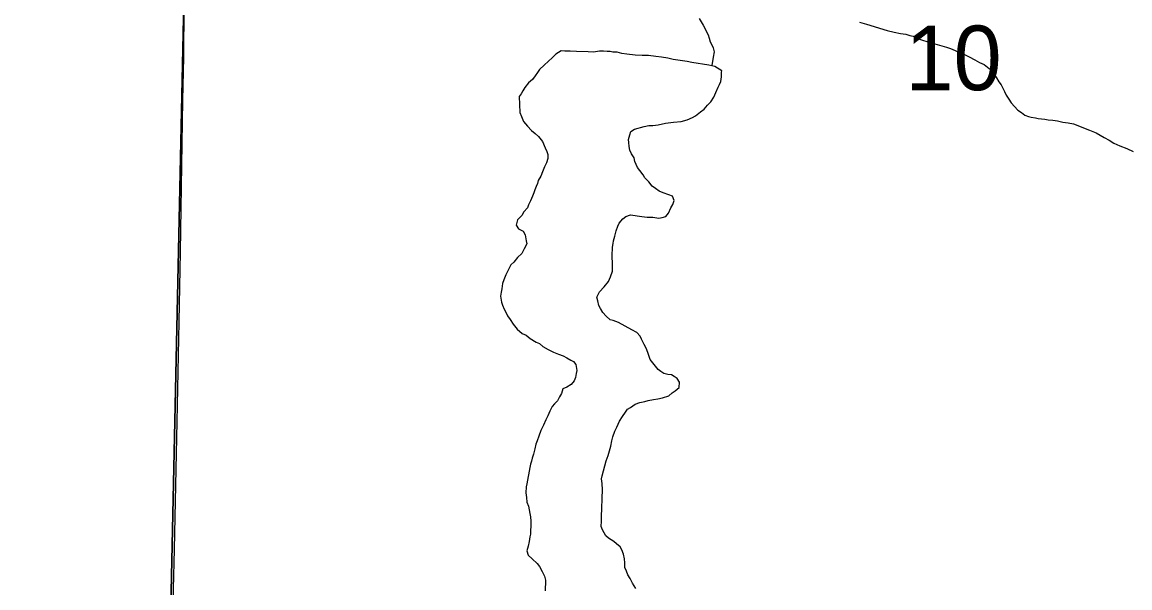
# Model space of a CAD drawing. Extents: x 2.4 to 73.1, y 4.5 to 25.6.
# Drawn here: x 34.9553 to 35.314, y 20.625 to 20.8082 of the extents above; entities that cross this region are included whole.
import ezdxf

# ---------------------------------------------------------------- set-up
doc = ezdxf.new("R2010")
doc.units = 0
for name, color, linetype in [('GM_X_County_Road', 7, 'Continuous'), ('GM_X_Minor_Lake', 7, 'Continuous'), ('GM_X_Minor_River', 7, 'Continuous'), ('GM_X_Section', 7, 'Continuous'), ('GM_X_Section_Text', 7, 'Continuous')]:
    doc.layers.add(name, color=color, linetype=linetype)

msp = doc.modelspace()

# ---------------------------------------------------------------- linework, layer by layer
at = {"layer": 'GM_X_County_Road'}
msp.add_lwpolyline([(35.00289, 20.55796), (35.00312, 20.57408), (35.00389, 20.61013), (35.00423, 20.62473), (35.00454, 20.63747), (35.00505, 20.65829), (35.00549, 20.6788), (35.00608, 20.71112), (35.00648, 20.73381), (35.00729, 20.78291), (35.0076, 20.79689), (35.00777, 20.81337), (35.00799, 20.82704), (35.00828, 20.84818), (35.00866, 20.87273), (35.00899, 20.89821), (35.00925, 20.9125), (35.00984, 20.94327), (35.0103, 20.96409), (35.01067, 20.98398), (35.01061, 20.98712), (35.01051, 20.99209)], dxfattribs=at)
at = {"layer": 'GM_X_Minor_Lake'}
for points in [[(35.18179, 20.79245), (35.17955, 20.7938), (35.17766, 20.79424), (35.17216, 20.79518), (35.17065, 20.79542), (35.16913, 20.79566), (35.16762, 20.7959), (35.1661, 20.79614), (35.1644, 20.79658), (35.16232, 20.79684), (35.16042, 20.79709), (35.15814, 20.79736), (35.15605, 20.79743), (35.15377, 20.7975), (35.15111, 20.79778), (35.1494, 20.79803), (35.14789, 20.79846), (35.14656, 20.7985), (35.14562, 20.79872), (35.14467, 20.79875), (35.14353, 20.79879), (35.14219, 20.79884), (35.14028, 20.79852), (35.13857, 20.79858), (35.13476, 20.7987), (35.13267, 20.79877), (35.13096, 20.79883), (35.12982, 20.79887), (35.12807, 20.79778), (35.12689, 20.79668), (35.12571, 20.79558), (35.12434, 20.79429), (35.12277, 20.79282), (35.12217, 20.79189), (35.12137, 20.79077), (35.12057, 20.78966), (35.11921, 20.78856), (35.11802, 20.78708), (35.11741, 20.78596), (35.11681, 20.78503), (35.11621, 20.7841), (35.11642, 20.77895), (35.11695, 20.7776), (35.11766, 20.77606), (35.11895, 20.77449), (35.12024, 20.77312), (35.12135, 20.77213), (35.12246, 20.77114), (35.12374, 20.76958), (35.12462, 20.76746), (35.12516, 20.7663), (35.12551, 20.76534), (35.12547, 20.76401), (35.12504, 20.76269), (35.12443, 20.76138), (35.12381, 20.75969), (35.12319, 20.75837), (35.12238, 20.75688), (35.12216, 20.75594), (35.12175, 20.755), (35.12133, 20.75387), (35.12092, 20.75293), (35.12051, 20.75181), (35.11989, 20.7503), (35.11928, 20.74899), (35.11886, 20.74806), (35.11768, 20.74676), (35.11707, 20.74564), (35.11569, 20.74416), (35.11526, 20.74247), (35.11598, 20.7413), (35.11748, 20.74049), (35.1182, 20.73932), (35.11852, 20.73741), (35.11868, 20.73646), (35.11787, 20.73477), (35.11706, 20.73328), (35.11569, 20.73199), (35.1145, 20.73051), (35.11351, 20.72959), (35.1127, 20.72809), (35.11189, 20.72641), (35.11126, 20.72472), (35.11085, 20.72359), (35.1106, 20.72188), (35.11037, 20.72075), (35.11014, 20.71943), (35.11046, 20.71751), (35.11081, 20.71655), (35.11134, 20.7152), (35.11188, 20.71423), (35.11242, 20.71307), (35.11333, 20.7119), (35.11423, 20.71035), (35.11551, 20.70879), (35.11718, 20.7074), (35.1185, 20.70679), (35.1198, 20.70579), (35.12167, 20.70459), (35.12279, 20.70417), (35.12391, 20.70318)], [(35.18179, 20.79245), (35.17955, 20.7938), (35.17766, 20.79424), (35.17216, 20.79518), (35.17065, 20.79542), (35.16913, 20.79566), (35.16762, 20.7959), (35.1661, 20.79614), (35.1644, 20.79658), (35.16232, 20.79684), (35.16042, 20.79709), (35.15814, 20.79736), (35.15605, 20.79743), (35.15377, 20.7975), (35.15111, 20.79778), (35.1494, 20.79803), (35.14789, 20.79846), (35.14656, 20.7985), (35.14562, 20.79872), (35.14467, 20.79875), (35.14353, 20.79879), (35.14219, 20.79884), (35.14028, 20.79852), (35.13857, 20.79858), (35.13476, 20.7987), (35.13267, 20.79877), (35.13096, 20.79883), (35.12982, 20.79887), (35.12807, 20.79778), (35.12689, 20.79668), (35.12571, 20.79558), (35.12434, 20.79429), (35.12277, 20.79282), (35.12217, 20.79189), (35.12137, 20.79077), (35.12057, 20.78966), (35.11921, 20.78856), (35.11802, 20.78708), (35.11741, 20.78596), (35.11681, 20.78503), (35.11621, 20.7841), (35.11642, 20.77895), (35.11695, 20.7776), (35.11766, 20.77606), (35.11895, 20.77449), (35.12024, 20.77312), (35.12135, 20.77213), (35.12246, 20.77114), (35.12374, 20.76958), (35.12462, 20.76746), (35.12516, 20.7663), (35.12551, 20.76534), (35.12547, 20.76401), (35.12504, 20.76269), (35.12443, 20.76138), (35.12381, 20.75969), (35.12319, 20.75837), (35.12238, 20.75688), (35.12216, 20.75594), (35.12175, 20.755), (35.12133, 20.75387), (35.12092, 20.75293), (35.12051, 20.75181), (35.11989, 20.7503), (35.11928, 20.74899), (35.11886, 20.74806), (35.11768, 20.74676), (35.11707, 20.74564), (35.11569, 20.74416), (35.11526, 20.74247), (35.11598, 20.7413), (35.11748, 20.74049), (35.1182, 20.73932), (35.11852, 20.73741), (35.11868, 20.73646), (35.11787, 20.73477), (35.11706, 20.73328), (35.11569, 20.73199), (35.1145, 20.73051), (35.11351, 20.72959), (35.1127, 20.72809), (35.11189, 20.72641), (35.11126, 20.72472), (35.11085, 20.72359), (35.1106, 20.72188), (35.11037, 20.72075), (35.11014, 20.71943), (35.11046, 20.71751), (35.11081, 20.71655), (35.11134, 20.7152), (35.11188, 20.71423), (35.11242, 20.71307), (35.11333, 20.7119), (35.11423, 20.71035), (35.11551, 20.70879), (35.11718, 20.7074), (35.1185, 20.70679), (35.1198, 20.70579), (35.12167, 20.70459), (35.12279, 20.70417), (35.12391, 20.70318)], [(35.15156, 20.77018), (35.15199, 20.77169), (35.15241, 20.77282), (35.15357, 20.77354), (35.15665, 20.77439), (35.15818, 20.77472), (35.15951, 20.77468), (35.16124, 20.775), (35.16354, 20.77549), (35.16621, 20.77579), (35.1687, 20.77608), (35.17062, 20.77659), (35.17235, 20.7773), (35.17332, 20.77783), (35.17489, 20.77911), (35.17606, 20.78003), (35.17724, 20.78132), (35.17823, 20.78243), (35.17923, 20.78392), (35.17985, 20.78542), (35.18067, 20.7871), (35.18108, 20.78804), (35.18149, 20.78898), (35.18173, 20.79049), (35.18177, 20.79201), (35.18179, 20.79245)], [(35.15156, 20.77018), (35.15199, 20.77169), (35.15241, 20.77282), (35.15357, 20.77354), (35.15665, 20.77439), (35.15818, 20.77472), (35.15951, 20.77468), (35.16124, 20.775), (35.16354, 20.77549), (35.16621, 20.77579), (35.1687, 20.77608), (35.17062, 20.77659), (35.17235, 20.7773), (35.17332, 20.77783), (35.17489, 20.77911), (35.17606, 20.78003), (35.17724, 20.78132), (35.17823, 20.78243), (35.17923, 20.78392), (35.17985, 20.78542), (35.18067, 20.7871), (35.18108, 20.78804), (35.18149, 20.78898), (35.18173, 20.79049), (35.18177, 20.79201), (35.18179, 20.79245)], [(35.14298, 20.65062), (35.14309, 20.65404), (35.14318, 20.6567), (35.14305, 20.6588), (35.14291, 20.66032), (35.14313, 20.66127), (35.14443, 20.66617), (35.14506, 20.66786), (35.14549, 20.66937), (35.14591, 20.67088), (35.14616, 20.67258), (35.14658, 20.6739), (35.14721, 20.67578), (35.14783, 20.67709), (35.14865, 20.67897), (35.14965, 20.68046), (35.15065, 20.68195), (35.15125, 20.68288), (35.15222, 20.68341), (35.15378, 20.6845), (35.15532, 20.68503), (35.15685, 20.68535), (35.158, 20.6857), (35.15973, 20.68602), (35.16107, 20.68617), (35.1626, 20.6865), (35.16472, 20.68719), (35.1657, 20.68811), (35.16667, 20.68883), (35.16804, 20.68993), (35.1681, 20.69164), (35.16737, 20.69281), (35.16644, 20.69341), (35.16551, 20.69401), (35.16436, 20.69405), (35.16304, 20.69447), (35.16211, 20.69507), (35.16118, 20.69567), (35.15862, 20.69899), (35.1581, 20.70053), (35.1574, 20.70246), (35.15668, 20.70381), (35.15578, 20.70556), (35.15543, 20.70652), (35.15433, 20.7077), (35.15264, 20.70851), (35.15058, 20.70972), (35.14834, 20.71094), (35.14664, 20.71156), (35.1457, 20.71179), (35.1444, 20.71297), (35.1433, 20.71415), (35.14258, 20.7155), (35.14204, 20.71647), (35.14171, 20.718), (35.14136, 20.71916), (35.14218, 20.72084), (35.14376, 20.7225), (35.14514, 20.72417), (35.14576, 20.72567), (35.14639, 20.72755), (35.14646, 20.72983), (35.14636, 20.7325), (35.14645, 20.73535), (35.14668, 20.73648), (35.14671, 20.73743), (35.14714, 20.73894), (35.14757, 20.74064), (35.14819, 20.74214), (35.1486, 20.74308), (35.14979, 20.74456), (35.15077, 20.74529), (35.15231, 20.74581), (35.15591, 20.74531), (35.15761, 20.74506), (35.15952, 20.745), (35.16141, 20.74475), (35.16256, 20.7449), (35.16371, 20.74524), (35.16451, 20.74636), (35.16533, 20.74804), (35.16593, 20.74916), (35.16636, 20.75048), (35.16583, 20.75183), (35.1647, 20.75225), (35.16282, 20.75288), (35.1615, 20.75349), (35.16039, 20.75429), (35.15927, 20.75509), (35.15817, 20.75646), (35.15688, 20.75783), (35.15634, 20.7588), (35.15524, 20.76017), (35.15451, 20.76114), (35.15362, 20.76308), (35.15347, 20.76422), (35.15256, 20.76558), (35.15202, 20.76674), (35.15187, 20.76789), (35.15172, 20.76923), (35.15156, 20.77018)], [(35.14298, 20.65062), (35.14309, 20.65404), (35.14318, 20.6567), (35.14305, 20.6588), (35.14291, 20.66032), (35.14313, 20.66127), (35.14443, 20.66617), (35.14506, 20.66786), (35.14549, 20.66937), (35.14591, 20.67088), (35.14616, 20.67258), (35.14658, 20.6739), (35.14721, 20.67578), (35.14783, 20.67709), (35.14865, 20.67897), (35.14965, 20.68046), (35.15065, 20.68195), (35.15125, 20.68288), (35.15222, 20.68341), (35.15378, 20.6845), (35.15532, 20.68503), (35.15685, 20.68535), (35.158, 20.6857), (35.15973, 20.68602), (35.16107, 20.68617), (35.1626, 20.6865), (35.16472, 20.68719), (35.1657, 20.68811), (35.16667, 20.68883), (35.16804, 20.68993), (35.1681, 20.69164), (35.16737, 20.69281), (35.16644, 20.69341), (35.16551, 20.69401), (35.16436, 20.69405), (35.16304, 20.69447), (35.16211, 20.69507), (35.16118, 20.69567), (35.15862, 20.69899), (35.1581, 20.70053), (35.1574, 20.70246), (35.15668, 20.70381), (35.15578, 20.70556), (35.15543, 20.70652), (35.15433, 20.7077), (35.15264, 20.70851), (35.15058, 20.70972), (35.14834, 20.71094), (35.14664, 20.71156), (35.1457, 20.71179), (35.1444, 20.71297), (35.1433, 20.71415), (35.14258, 20.7155), (35.14204, 20.71647), (35.14171, 20.718), (35.14136, 20.71916), (35.14218, 20.72084), (35.14376, 20.7225), (35.14514, 20.72417), (35.14576, 20.72567), (35.14639, 20.72755), (35.14646, 20.72983), (35.14636, 20.7325), (35.14645, 20.73535), (35.14668, 20.73648), (35.14671, 20.73743), (35.14714, 20.73894), (35.14757, 20.74064), (35.14819, 20.74214), (35.1486, 20.74308), (35.14979, 20.74456), (35.15077, 20.74529), (35.15231, 20.74581), (35.15591, 20.74531), (35.15761, 20.74506), (35.15952, 20.745), (35.16141, 20.74475), (35.16256, 20.7449), (35.16371, 20.74524), (35.16451, 20.74636), (35.16533, 20.74804), (35.16593, 20.74916), (35.16636, 20.75048), (35.16583, 20.75183), (35.1647, 20.75225), (35.16282, 20.75288), (35.1615, 20.75349), (35.16039, 20.75429), (35.15927, 20.75509), (35.15817, 20.75646), (35.15688, 20.75783), (35.15634, 20.7588), (35.15524, 20.76017), (35.15451, 20.76114), (35.15362, 20.76308), (35.15347, 20.76422), (35.15256, 20.76558), (35.15202, 20.76674), (35.15187, 20.76789), (35.15172, 20.76923), (35.15156, 20.77018)], [(35.12391, 20.70318), (35.12559, 20.70218), (35.12728, 20.70136), (35.12897, 20.70073), (35.13047, 20.70011), (35.1316, 20.6995), (35.1329, 20.6987), (35.13384, 20.69829), (35.13457, 20.69731), (35.13489, 20.6954), (35.13467, 20.69446), (35.13444, 20.69313), (35.13402, 20.69201), (35.13303, 20.6909), (35.13167, 20.68999), (35.13032, 20.68947), (35.12989, 20.68796), (35.12929, 20.68684), (35.12867, 20.68552), (35.12769, 20.68461), (35.1269, 20.68368), (35.12609, 20.68219), (35.12547, 20.68068), (35.12486, 20.67937), (35.12404, 20.67769), (35.12323, 20.676), (35.1226, 20.67412), (35.12198, 20.67262), (35.12156, 20.67149), (35.12132, 20.66998), (35.12089, 20.66828), (35.12046, 20.66696), (35.12024, 20.66602), (35.11983, 20.66508), (35.11961, 20.66395), (35.11867, 20.65865), (35.11845, 20.65771), (35.11839, 20.65581), (35.11853, 20.65428), (35.11868, 20.65275), (35.11921, 20.65141), (35.1197, 20.64911), (35.11986, 20.64796), (35.12, 20.64662), (35.11997, 20.64567), (35.11994, 20.64472), (35.11991, 20.64377), (35.11987, 20.64244), (35.11965, 20.6415), (35.11941, 20.63998), (35.11917, 20.63847), (35.11874, 20.63696), (35.11908, 20.63562), (35.12038, 20.63444), (35.12204, 20.63286), (35.12277, 20.63188), (35.12367, 20.63033), (35.12439, 20.62879), (35.12472, 20.62744), (35.12469, 20.6263), (35.12465, 20.62516), (35.12461, 20.62402)], [(35.12391, 20.70318), (35.12559, 20.70218), (35.12728, 20.70136), (35.12897, 20.70073), (35.13047, 20.70011), (35.1316, 20.6995), (35.1329, 20.6987), (35.13384, 20.69829), (35.13457, 20.69731), (35.13489, 20.6954), (35.13467, 20.69446), (35.13444, 20.69313), (35.13402, 20.69201), (35.13303, 20.6909), (35.13167, 20.68999), (35.13032, 20.68947), (35.12989, 20.68796), (35.12929, 20.68684), (35.12867, 20.68552), (35.12769, 20.68461), (35.1269, 20.68368), (35.12609, 20.68219), (35.12547, 20.68068), (35.12486, 20.67937), (35.12404, 20.67769), (35.12323, 20.676), (35.1226, 20.67412), (35.12198, 20.67262), (35.12156, 20.67149), (35.12132, 20.66998), (35.12089, 20.66828), (35.12046, 20.66696), (35.12024, 20.66602), (35.11983, 20.66508), (35.11961, 20.66395), (35.11867, 20.65865), (35.11845, 20.65771), (35.11839, 20.65581), (35.11853, 20.65428), (35.11868, 20.65275), (35.11921, 20.65141), (35.1197, 20.64911), (35.11986, 20.64796), (35.12, 20.64662), (35.11997, 20.64567), (35.11994, 20.64472), (35.11991, 20.64377), (35.11987, 20.64244), (35.11965, 20.6415), (35.11941, 20.63998), (35.11917, 20.63847), (35.11874, 20.63696), (35.11908, 20.63562), (35.12038, 20.63444), (35.12204, 20.63286), (35.12277, 20.63188), (35.12367, 20.63033), (35.12439, 20.62879), (35.12472, 20.62744), (35.12469, 20.6263), (35.12465, 20.62516), (35.12461, 20.62402)], [(35.15396, 20.62477), (35.15288, 20.62651), (35.15216, 20.62806), (35.15144, 20.62923), (35.15091, 20.63038), (35.15037, 20.63154), (35.15042, 20.63306), (35.15027, 20.6344), (35.14994, 20.63593), (35.14941, 20.63728), (35.14887, 20.63825), (35.14776, 20.63924), (35.14683, 20.64003), (35.14515, 20.64104), (35.14423, 20.64183), (35.14314, 20.64377), (35.1428, 20.64492), (35.14285, 20.64663), (35.14291, 20.64834), (35.14298, 20.65062)], [(35.15396, 20.62477), (35.15288, 20.62651), (35.15216, 20.62806), (35.15144, 20.62923), (35.15091, 20.63038), (35.15037, 20.63154), (35.15042, 20.63306), (35.15027, 20.6344), (35.14994, 20.63593), (35.14941, 20.63728), (35.14887, 20.63825), (35.14776, 20.63924), (35.14683, 20.64003), (35.14515, 20.64104), (35.14423, 20.64183), (35.14314, 20.64377), (35.1428, 20.64492), (35.14285, 20.64663), (35.14291, 20.64834), (35.14298, 20.65062)]]:
    msp.add_lwpolyline(points, dxfattribs=at)
at = {"layer": 'GM_X_Minor_River'}
for points in [[(35.17452, 20.80937), (35.17579, 20.80724), (35.17633, 20.80627), (35.17686, 20.80511), (35.1774, 20.80414), (35.17775, 20.80299), (35.17809, 20.80184), (35.17863, 20.80087), (35.17898, 20.7999), (35.17932, 20.79856), (35.17907, 20.79686), (35.17855, 20.79414)], [(35.22647, 20.80823), (35.22873, 20.80758), (35.23533, 20.80546), (35.2376, 20.80501), (35.23968, 20.80456), (35.24139, 20.80431), (35.24271, 20.80389), (35.24384, 20.80366), (35.24497, 20.80305), (35.24647, 20.80243), (35.24854, 20.80179), (35.25005, 20.80136), (35.25156, 20.80093), (35.25307, 20.8005), (35.25458, 20.80007), (35.2559, 20.79965), (35.25741, 20.79903), (35.25872, 20.79841), (35.26022, 20.79779), (35.26191, 20.79697), (35.26378, 20.79596), (35.26528, 20.79515), (35.26678, 20.79453), (35.26845, 20.79315), (35.26938, 20.79235), (35.26992, 20.79138), (35.27083, 20.79021), (35.27155, 20.78886), (35.27228, 20.78788), (35.27336, 20.78575), (35.27389, 20.78459), (35.2748, 20.78323), (35.27553, 20.78207), (35.27663, 20.78089), (35.27774, 20.77971), (35.27885, 20.77891), (35.27997, 20.77812), (35.2811, 20.7777), (35.28204, 20.77748), (35.28337, 20.77724), (35.28431, 20.77702), (35.2864, 20.77676), (35.28754, 20.77654), (35.28906, 20.77649), (35.29057, 20.77624), (35.29227, 20.77581), (35.29398, 20.77556), (35.29569, 20.77531), (35.30095, 20.77324), (35.30302, 20.77241), (35.30563, 20.7708), (35.30732, 20.76998), (35.30881, 20.76898), (35.31069, 20.76816), (35.31295, 20.76732), (35.31501, 20.76631)]]:
    msp.add_lwpolyline(points, dxfattribs=at)
at = {"layer": 'GM_X_Section'}
for points in [[(35.01295, 21.06066), (35.00213, 20.55856), (34.50366, 20.57062), (34.5135, 21.07124)], [(35.51178, 21.04783), (35.50361, 20.54567), (35.00213, 20.55856), (35.01295, 21.06066)]]:
    msp.add_lwpolyline(points, close=True, dxfattribs=at)

# ---------------------------------------------------------------- texts
at = {"layer": 'GM_X_Section_Text'}
msp.add_text('10', height=0.020928, rotation=0, dxfattribs=at).set_placement((35.24131, 20.78616))

doc.saveas('drawing.dxf')
